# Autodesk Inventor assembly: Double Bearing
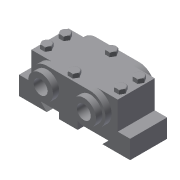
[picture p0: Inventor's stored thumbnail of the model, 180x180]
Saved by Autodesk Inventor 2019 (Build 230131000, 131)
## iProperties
Shininess: 64.0
Length Units: 11269
Angle Units: 11279
Time Units: 11290
Mass Units: 11283
Length Display Precision: 3
Angle Display Precision: 2
Created: 2002-02
Part Number: Double Bearing
Document SubType Name: Assembly
Designer: ***
Density: 0.0
Volumn: 0.0
Area: 0.0
PropertySet Name: Model Information
Control State: 0
Master: False
Checked Out: False
Author: ***
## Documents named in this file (5)
- E:\_Deepak\Inventor\Projects\Autodesk Inventor_2019_Project\Resources\Inventor_2018_tut\c12_Inv_2019_tut\c12_Inv_tut_2019\c12_tut02_inv\Double Bearing.iam
- E:\_Deepak\Inventor\Projects\Autodesk Inventor_2019_Project\Resources\Inventor_2018_tut\c12_Inv_2019_tut\c12_Inv_tut_2019\c12_tut02_inv\Base.ipt
- E:\_Deepak\Inventor\Projects\Autodesk Inventor_2019_Project\Resources\Inventor_2018_tut\c12_Inv_2019_tut\c12_Inv_tut_2019\c12_tut02_inv\Cap.ipt
- E:\_Deepak\Inventor\Projects\Autodesk Inventor_2019_Project\Resources\Inventor_2018_tut\c12_Inv_2019_tut\c12_Inv_tut_2019\c12_tut02_inv\Bushing.ipt
- E:\_Deepak\Inventor\Projects\Autodesk Inventor_2019_Project\Resources\Inventor_2018_tut\c12_Inv_2019_tut\c12_Inv_tut_2019\c12_tut02_inv\Bolt.ipt
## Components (10 placed, 4 different names)
1. Base:1 — Insert:1, Insert:2
2. Cap:1 — Insert:1, Insert:2, Insert:3, Insert:4, Insert:5, Insert:6
3. Bushing:1 — Insert:3
4. Bushing:2 — Insert:4
5. Bolt:1 — Insert:5
6. Bolt:6
7. Bolt:7
8. Bolt:8
9. Bolt:5 — Insert:6
10. Bolt:9
## Component patterns: Component Pattern 1 (4 elements), Component Pattern 2 (2 elements)
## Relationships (6: Insert 6)
- Insert:1: Base:1 ↔ Cap:1
- Insert:2: Base:1 ↔ Cap:1
- Insert:3: Cap:1 ↔ Bushing:1
- Insert:4: Cap:1 ↔ Bushing:2
- Insert:5: Cap:1 ↔ Bolt:1
- Insert:6: Cap:1 ↔ Bolt:5
